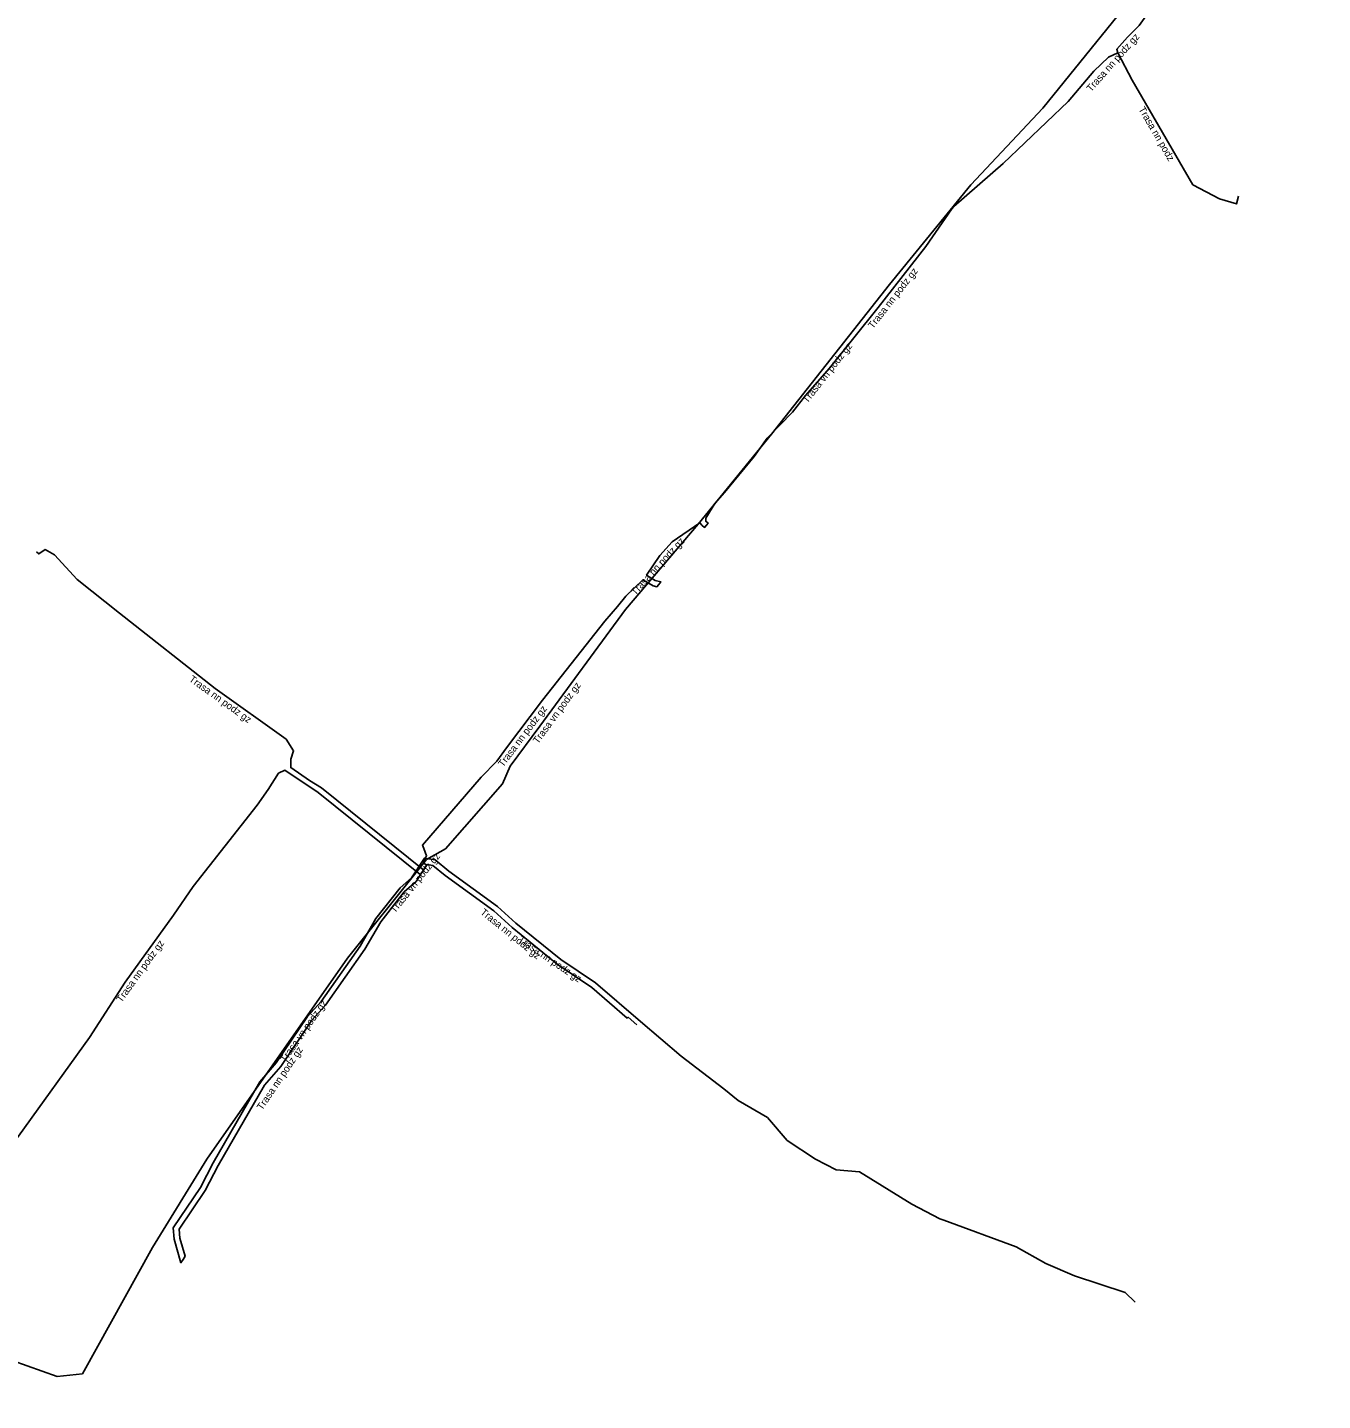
# Model space of a CAD drawing. Extents: x -686919 to -686577, y -972514 to -971911.
# Drawn here: x -686744.6 to -686653.9, y -972223.1 to -972126.9 of the extents above; entities that cross this region are included whole.
import ezdxf

# ---------------------------------------------------------------- set-up
doc = ezdxf.new("R2010")
doc.units = 0
for name, color, linetype in [('Popiskový text - Ostatní atributy Trasy', 7, 'Continuous'), ('Spojnice NN', 7, 'Continuous'), ('Spojnice VN', 7, 'Continuous')]:
    doc.layers.add(name, color=color, linetype=linetype)

msp = doc.modelspace()

# ---------------------------------------------------------------- linework, layer by layer
at = {"layer": 'Spojnice NN'}
for points in [[(-686653.98, -972111.1), (-686656.05, -972113.5), (-686657.31, -972114.86), (-686659.1, -972117.4), (-686660.64, -972119.44), (-686662.07, -972120.92), (-686663.96, -972123.29), (-686665.4, -972124.84), (-686666.79, -972126.8), (-686667.59, -972127.61)], [(-686667.59, -972127.61), (-686668.35, -972128.47), (-686668.27, -972128.72)], [(-686668.27, -972128.72), (-686668.93, -972129.02), (-686669.95, -972130.01), (-686671.76, -972132.12), (-686676.3, -972136.46), (-686679.76, -972139.47), (-686679.896, -972139.641), (-686681.72, -972142.27), (-686685.06, -972146.56), (-686688.46, -972150.81), (-686690.14, -972152.71), (-686691.07, -972153.89), (-686692.84, -972155.69), (-686693.74, -972156.99), (-686695.81, -972159.51), (-686696.5, -972160.27), (-686697.13, -972161.31), (-686697.131, -972161.523), (-686696.966, -972161.643), (-686697.09, -972161.8)], [(-686659.826, -972138.749), (-686659.973, -972139.296), (-686661.166, -972138.951), (-686663.034, -972137.949), (-686667.269, -972130.638), (-686668.27, -972128.72)], [(-686697.09, -972161.8), (-686697.213, -972161.957), (-686697.385, -972161.829), (-686697.55, -972161.64), (-686699.48, -972162.96), (-686700.35, -972163.91), (-686701.279, -972165.303), (-686700.673, -972165.673), (-686700.279, -972165.765), (-686700.41, -972165.94)], [(-686743.99, -972163.67), (-686743.842, -972163.805), (-686743.39, -972163.51), (-686742.75, -972163.87), (-686741.15, -972165.61), (-686738.18, -972167.96), (-686731.48, -972173.23), (-686726.52, -972176.78), (-686726, -972177.59), (-686726.18, -972178.19), (-686726.194, -972178.77), (-686724.891, -972179.682), (-686724.046, -972180.185), (-686716.885, -972185.954), (-686717.01, -972186.11)], [(-686700.41, -972165.94), (-686700.551, -972166.112), (-686700.827, -972166.047), (-686701.539, -972165.614), (-686702.73, -972166.76), (-686703.322, -972167.497), (-686704.21, -972168.52), (-686708.57, -972174.04), (-686711.083, -972177.383), (-686711.77, -972178.32), (-686712.87, -972179.44), (-686716.96, -972184.2), (-686716.868, -972184.445), (-686716.688, -972184.958), (-686716.932, -972185.41), (-686716.683, -972185.603), (-686717.01, -972186.11)], [(-686717.01, -972186.11), (-686717.135, -972186.266), (-686724.274, -972180.515), (-686726.62, -972178.96), (-686727.05, -972179.17), (-686727.784, -972180.303), (-686728.55, -972181.41), (-686733.03, -972187.11), (-686734.41, -972189.1), (-686737.8, -972193.81), (-686740.28, -972197.68), (-686745.27, -972204.58), (-686747.73, -972207.84), (-686750.23, -972210.23), (-686751.88, -972213.78), (-686751.602, -972213.769), (-686751.387, -972213.881), (-686751.67, -972214.41)], [(-686733.74, -972213.22), (-686733.882, -972213.45), (-686734.358, -972211.806), (-686734.425, -972210.996), (-686732.522, -972208.188), (-686731.636, -972206.454), (-686728.363, -972200.773), (-686727.209, -972199.458), (-686725.028, -972196.216), (-686724.066, -972195.155), (-686721.339, -972191.282), (-686720.226, -972189.348), (-686718.536, -972187.192), (-686717.743, -972186.491), (-686716.83, -972185.114), (-686716.084, -972185.242), (-686715.137, -972186.022), (-686711.724, -972188.505), (-686710.43, -972189.678), (-686707.291, -972192.209), (-686704.858, -972193.851), (-686701.709, -972196.543), (-686698.855, -972198.984), (-686695.867, -972201.273), (-686694.856, -972202.085), (-686692.819, -972203.275), (-686691.437, -972204.878), (-686689.449, -972206.187), (-686687.993, -972206.944), (-686686.376, -972207.085), (-686682.711, -972209.336), (-686680.742, -972210.365), (-686680.457, -972210.46), (-686675.395, -972212.328), (-686673.331, -972213.5), (-686671.309, -972214.363), (-686667.77, -972215.53), (-686667.07, -972216.22)], [(-686717.01, -972186.11), (-686716.645, -972185.551), (-686716.256, -972185.618), (-686715.383, -972186.338), (-686711.976, -972188.815), (-686710.69, -972189.982), (-686707.529, -972192.531), (-686705.102, -972194.169), (-686702.626, -972196.314), (-686702.577, -972196.26), (-686701.97, -972196.78)], [(-686733.74, -972213.22), (-686733.599, -972212.989), (-686733.962, -972211.734), (-686734.015, -972211.104), (-686732.178, -972208.392), (-686731.284, -972206.646), (-686728.037, -972201.007), (-686726.891, -972199.702), (-686724.712, -972196.464), (-686723.754, -972195.405), (-686721.001, -972191.498), (-686719.894, -972189.572), (-686718.244, -972187.468), (-686717.422, -972186.74), (-686717.01, -972186.11)]]:
    msp.add_lwpolyline(points, dxfattribs=at)
at = {"layer": 'Spojnice VN'}
for points in [[(-686678.56, -972137.96), (-686673.53, -972132.59), (-686665.66, -972122.86), (-686658.33, -972113.25), (-686653.943, -972107.859)], [(-686697.66, -972161.72), (-686692.54, -972155.43), (-686684.27, -972144.95), (-686678.56, -972137.96)], [(-686716.69, -972185.2), (-686715.36, -972184.46), (-686711.36, -972179.91), (-686710.84, -972178.67), (-686708.75, -972175.87), (-686702.76, -972167.69), (-686697.66, -972161.72)], [(-686732.08, -972206.19), (-686722.21, -972192.11), (-686717.257, -972185.91)], [(-686717.257, -972185.91), (-686716.69, -972185.2)], [(-686797.29, -972193.43), (-686790.08, -972197.29), (-686787.17, -972198.94), (-686781.25, -972202.53), (-686776.24, -972206.1), (-686766.65, -972214.07), (-686760.84, -972219.91), (-686758.31, -972222.72), (-686757.1, -972223.1), (-686753.32, -972218.34), (-686752.77, -972217.79), (-686751.65, -972218.22), (-686749.93, -972218.81), (-686742.56, -972221.41), (-686740.79, -972221.22), (-686735.88, -972212.38), (-686732.08, -972206.19)]]:
    msp.add_lwpolyline(points, dxfattribs=at)

# ---------------------------------------------------------------- texts
at = {"layer": 'Popiskový text - Ostatní atributy Trasy'}
for s, rotation, p in [('Trasa nn podz gz', 48.53229, (-686670.148, -972131.486)), ('Trasa nn podz', 300.08217, (-686666.849, -972132.659)), ('Trasa nn podz gz', 52.09729, (-686685.422, -972148.083)), ('Trasa vn podz gz', 51.72225, (-686690.023, -972153.29)), ('Trasa nn podz gz', 47.51688, (-686702.067, -972166.747)), ('Trasa nn podz gz', 324.40772, (-686733.363, -972172.682)), ('Trasa vn podz gz', 53.78566, (-686708.88, -972177.148)), ('Trasa nn podz gz', 53.06708, (-686711.322, -972178.783)), ('Trasa vn podz gz', 51.38943, (-686718.895, -972189.004)), ('Trasa nn podz gz', 321.11763, (-686712.964, -972188.983)), ('Trasa nn podz gz', 325.9851, (-686710.329, -972190.943)), ('Trasa nn podz gz', 54.25573, (-686738.046, -972195.263)), ('Trasa vn podz gz', 54.96976, (-686726.57, -972199.463)), ('Trasa nn podz gz', 56.06157, (-686728.2, -972202.812))]:
    msp.add_text(s, height=0.5, rotation=rotation, dxfattribs=at).set_placement(p)

doc.saveas('drawing.dxf')
